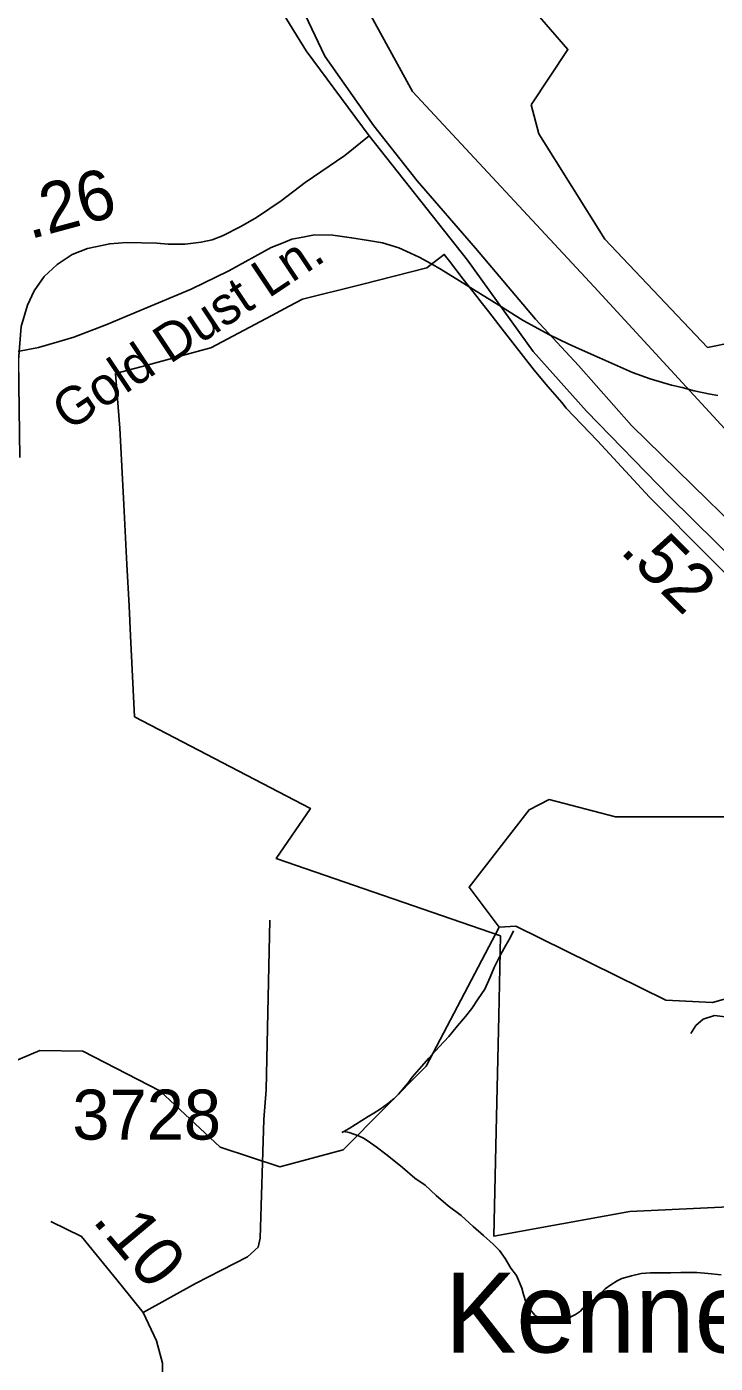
# Model space of a CAD drawing. Extents: x 2001466 to 2224147, y 644118 to 847247.
# Drawn here: x 2072387 to 2074109, y 650618 to 653960 of the extents above; entities that cross this region are included whole.
import ezdxf

# ---------------------------------------------------------------- set-up
doc = ezdxf.new("R2010")
doc.units = 0
for name, color, linetype in [('Exist Aviation Public Landing Strip paved', 7, 'Continuous'), ('Exist Boundary Political City Limit New', 7, 'Continuous'), ('Exist Civil Demographics Community Label', 7, 'Continuous'), ('Exist Hydrographic Misc Water Feature', 7, 'Continuous'), ('Exist Railroad Mainline', 7, 'Continuous'), ('Exist Road Non-System Type 51', 7, 'Continuous'), ('Exist Road Primary NC Attributed', 7, 'Continuous'), ('Exist Road Primary NC Service Mileage Hundredths English Label', 7, 'Continuous'), ('Exist Road Secondary Mileage Hundredths English Label', 7, 'Continuous'), ('Exist Road Secondary Type 51 Attributed', 7, 'Continuous'), ('Exist Road Secondary Type 51 Label', 7, 'Continuous'), ('Exist Road Secondary Type 51 Number Label', 7, 'Continuous'), ('Map Preparation Boundary City Limit Buffer Line', 7, 'Continuous')]:
    doc.layers.add(name, color=color, linetype=linetype)

msp = doc.modelspace()

# ---------------------------------------------------------------- linework, layer by layer
at = {"layer": 'Exist Aviation Public Landing Strip paved'}
msp.add_lwpolyline([(2075026.1, 652255.3), (2074894.2, 652255.3), (2074788.8, 652275.1), (2074657, 652367.4), (2074334, 652736.7), (2073806.7, 653310.3), (2073351.9, 653798.2), (2073206.2, 654065.5), (2073437.6, 654253.2), (2073740.8, 653903.7), (2073648.5, 653765.3), (2073668.3, 653692.7), (2073833, 653429), (2074090.1, 653158.7), (2074156, 653171.9), (2074248.3, 653251), (2074867.9, 652644.4), (2075006.3, 652459.7), (2075012.9, 652334.5), (2075026.1, 652255.3)], dxfattribs=at)
at = {"layer": 'Exist Boundary Political City Limit New'}
msp.add_lwpolyline([(2074160.8, 651010.1), (2073895.5, 650997.6), (2073555.4, 650936.3), (2073561.1, 651198.3), (2073567.6, 651486.8), (2073572.1, 651687), (2073011.2, 651880.7), (2073096.5, 652005.9), (2072656.8, 652235.1), (2072646.8, 652437.2), (2072643, 652512.2), (2072637.6, 652615.8), (2072629.9, 652765.7), (2072620, 652956.5), (2072609.4, 653093), (2072688.1, 653114.4), (2072831.5, 653153.5), (2072847.8, 653157.8), (2072999.8, 653238.4), (2073043.9, 653261.8), (2073076.6, 653279.2), (2073224.4, 653316.2), (2073388, 653357.2), (2073414, 653377.5), (2073431.5, 653391.1), (2073444.6, 653374.6), (2073478.6, 653329.2), (2073512.6, 653286.1), (2073523.9, 653271.7), (2073542.9, 653247.1), (2073576, 653204.3), (2073656.6, 653101.9), (2073690.5, 653060.4), (2073725.8, 653020.4), (2073736.8, 653006.6), (2073814.5, 652924.9), (2073944.6, 652784.2), (2074844, 651880.9)], dxfattribs=at)
at = {"layer": 'Exist Hydrographic Misc Water Feature'}
msp.add_line((2074096.3, 653042), (2074115.8, 653038), dxfattribs=at)
for points in [[(2073028.8, 653420.2), (2073050.5, 653429), (2073077.6, 653434.2)], [(2073028.8, 653420.2), (2073050.5, 653429), (2073077.6, 653434.2)], [(2073077.6, 653434.2), (2073106.7, 653439.9), (2073153, 653439), (2073182.2, 653435.1)], [(2073077.6, 653434.2), (2073106.7, 653439.9), (2073153, 653439), (2073182.2, 653435.1)], [(2073182.2, 653435.1), (2073199.8, 653432.9), (2073241.8, 653425.7)], [(2073182.2, 653435.1), (2073199.8, 653432.9), (2073241.8, 653425.7)], [(2073241.8, 653425.7), (2073276.7, 653419.8), (2073317.9, 653407.9), (2073346.8, 653394.3)], [(2073241.8, 653425.7), (2073276.7, 653419.8), (2073317.9, 653407.9), (2073346.8, 653394.3)], [(2072635.1, 653235.6), (2072798.5, 653304.5), (2072892.8, 653349.9), (2072998.6, 653408.1), (2073028.8, 653420.2)], [(2072635.1, 653235.6), (2072798.5, 653304.5), (2072892.8, 653349.9), (2072998.6, 653408.1), (2073028.8, 653420.2)], [(2073346.8, 653394.3), (2073368.8, 653384.2), (2073397.5, 653368.1)], [(2073346.8, 653394.3), (2073368.8, 653384.2), (2073397.5, 653368.1)], [(2073397.5, 653368.1), (2073423.9, 653353.4), (2073567.7, 653263.8)], [(2073397.5, 653368.1), (2073423.9, 653353.4), (2073567.7, 653263.8)], [(2073567.7, 653263.8), (2073628.8, 653225.8), (2073694.8, 653190), (2073741.5, 653167.6)], [(2073567.7, 653263.8), (2073628.8, 653225.8), (2073694.8, 653190), (2073741.5, 653167.6)], [(2072468.4, 653173.3), (2072504.7, 653184), (2072587.7, 653215.6), (2072635.1, 653235.6)], [(2072468.4, 653173.3), (2072504.7, 653184), (2072587.7, 653215.6), (2072635.1, 653235.6)], [(2072342.7, 653144.5), (2072416.7, 653158), (2072468.4, 653173.3)], [(2072342.7, 653144.5), (2072416.7, 653158), (2072468.4, 653173.3)], [(2073741.5, 653167.6), (2073768.6, 653154.7), (2073820.1, 653132.2)], [(2073741.5, 653167.6), (2073768.6, 653154.7), (2073820.1, 653132.2)], [(2073820.1, 653132.2), (2073902.7, 653096), (2073946.6, 653079.9)], [(2073820.1, 653132.2), (2073902.7, 653096), (2073946.6, 653079.9)], [(2073946.6, 653079.9), (2073999.7, 653064.5), (2074026.4, 653057.9)], [(2073946.6, 653079.9), (2073999.7, 653064.5), (2074026.4, 653057.9)], [(2074026.4, 653057.9), (2074056.9, 653050.2), (2074096.3, 653042)], [(2074026.4, 653057.9), (2074056.9, 653050.2), (2074096.3, 653042)], [(2073568.7, 651708.7), (2073493.6, 651808.7), (2073643.7, 652002.5), (2073693.8, 652027.7), (2073859.7, 651984.9), (2074176.7, 651985), (2074448.4, 651957.8)], [(2072946.5, 651133.7), (2073019.8, 651109.6), (2073178.7, 651152.4), (2073386.6, 651361.4), (2073568.7, 651708.7)], [(2073604.4, 651699.9), (2073596.4, 651681.9), (2073584.3, 651661.9), (2073572.4, 651639.9), (2073556.4, 651607.8), (2073546.5, 651583.8), (2073532.6, 651553.8), (2073516.6, 651529.7), (2073500.6, 651505.7), (2073484.6, 651485.7), (2073464.7, 651461.7), (2073442.8, 651435.6), (2073418.8, 651409.6), (2073393, 651381.5), (2073369, 651353.5), (2073351.1, 651333.5), (2073341.1, 651319.5), (2073331, 651307.5), (2073317.1, 651291.4), (2073305.2, 651279.4), (2073289.2, 651267.4), (2073271.2, 651253.4), (2073255.2, 651243.4), (2073241.2, 651235.3), (2073225.2, 651225.3), (2073209.2, 651215.2), (2073193.2, 651205.2), (2073179.9, 651197.7), (2073175.4, 651195.2)], [(2074449.2, 651617.6), (2074102.6, 651520.8), (2073985.8, 651526.4), (2073610.7, 651711.2), (2073568.7, 651708.7)], [(2070697, 649864.9), (2070730.6, 650053.8), (2070930.7, 650472.9), (2071104.8, 650722), (2071270.7, 650905.6), (2071545.6, 651096.9), (2071870.7, 651241.3), (2072161.6, 651291.1), (2072419.8, 651400.7), (2072527.6, 651398.4), (2072719.8, 651299.4), (2072870.7, 651158.6), (2072946.5, 651133.7)], [(2073175.4, 651195.2), (2073179.9, 651197.7), (2073193.2, 651195.2), (2073205.3, 651191.2), (2073217.2, 651187.3), (2073229.3, 651181.3), (2073241.2, 651173.3), (2073261.3, 651159.3), (2073285.5, 651141.4), (2073305.4, 651125.4), (2073327.3, 651107.5), (2073357.5, 651081.5), (2073383.5, 651063.6), (2073411.6, 651037.6), (2073441.6, 651011.8), (2073473.7, 650987.8), (2073503.7, 650959.9), (2073529.7, 650937.9), (2073553.7, 650916), (2073569.7, 650900), (2073583.9, 650880.1), (2073597.8, 650856.1), (2073612, 650838.1), (2073620, 650820.1), (2073625.9, 650806.1), (2073630, 650790.1), (2073635.9, 650772.2), (2073640, 650762.2), (2073650.1, 650748.2), (2073658.1, 650738.2), (2073667.9, 650732.2), (2073682.1, 650726.2), (2073690.1, 650724.2), (2073700.1, 650722.3), (2073710, 650720.3), (2073718, 650722.3), (2073726, 650724.3), (2073742, 650730.4), (2073748.1, 650734.4), (2073760, 650740.4), (2073772.1, 650748.4), (2073778, 650756.4), (2073792, 650768.4), (2073803.9, 650776.5), (2073817.8, 650788.5), (2073833.8, 650804.5), (2073848, 650814.6), (2073863.8, 650824.5), (2073875.9, 650830.6), (2073899.8, 650836.6), (2073923.8, 650842.7), (2073947.8, 650844.7), (2073973.9, 650844.7), (2073997.9, 650844.8), (2074023.7, 650844.9), (2074063.7, 650844.9), (2074091.8, 650843), (2074123.8, 650839.1)]]:
    msp.add_lwpolyline(points, dxfattribs=at)
at = {"layer": 'Exist Railroad Mainline'}
msp.add_lwpolyline([(2074447.8, 652429.1), (2074089.7, 652777), (2073899.5, 652963), (2073767.5, 653112.9), (2073659.5, 653228.9), (2073509.3, 653406.7), (2073363.3, 653574.7), (2073255.2, 653712.7), (2073133.1, 653886.6), (2073043, 654076.6), (2072967, 654272.8), (2072914.7, 654476.6), (2072848.5, 654812.8), (2072811.5, 655023.4), (2072778.4, 655210.8), (2072702.2, 655610.9), (2072633.9, 656000.9), (2072585.7, 656437.2), (2072559.3, 656635.2), (2072537.3, 656822.6)], dxfattribs=at)
at = {"layer": 'Exist Road Non-System Type 51'}
for points in [[(2072678.2, 650745.3), (2072809.3, 650817.6), (2072938.9, 650884.5), (2072965.6, 650908.6), (2072971, 650931.3), (2072980.3, 651228.2), (2072985.7, 651301.7), (2072995, 651726.4)], [(2074147.4, 651483), (2074107.5, 651487.8), (2074079.3, 651478.4), (2074061, 651462.7), (2074048.5, 651443)]]:
    msp.add_lwpolyline(points, dxfattribs=at)
at = {"layer": 'Exist Road Primary NC Attributed'}
for points in [[(2073243.5, 653687.9), (2073085.9, 653900.1), (2073002.7, 654036.3), (2072949.3, 654163), (2072905.3, 654306.5), (2072862.9, 654505.4), (2072821.6, 654799.7), (2072790.2, 655036.4), (2072748.4, 655193.5), (2072710.7, 655340.1), (2072652.1, 655493)], [(2075058.1, 651633.9), (2074984.8, 651747), (2074910.5, 651840.2), (2074764.5, 651996.2), (2074516, 652245.5), (2074289.4, 652495.8), (2073995.3, 652785.8), (2073787, 652999.5), (2073653.6, 653148.2), (2073489.3, 653376.5), (2073243.5, 653687.9)]]:
    msp.add_lwpolyline(points, dxfattribs=at)
at = {"layer": 'Exist Road Secondary Type 51 Attributed'}
for points in [[(2073243.5, 653687.9), (2073182.6, 653638.7), (2073083.2, 653571.2), (2073023.3, 653524.7), (2072961.8, 653483.4), (2072922.6, 653460.6), (2072876.4, 653437.5), (2072850.6, 653427.4), (2072823.7, 653421.8), (2072783.2, 653416.9), (2072740.5, 653416.9), (2072712.7, 653418.9), (2072636.2, 653420.9), (2072594.5, 653417.9), (2072539.1, 653405.8), (2072500.4, 653390.6), (2072462.9, 653365.8), (2072430.6, 653335.7), (2072405.4, 653300), (2072389, 653264.4), (2072372.7, 653211), (2072366.7, 653126.3), (2072369.9, 652883)], [(2072726.8, 650535.1), (2072726.8, 650618.6), (2072712, 650674.6), (2072678.2, 650745.3), (2072623.4, 650814), (2072524.1, 650935.5), (2072447.1, 650972.4)]]:
    msp.add_lwpolyline(points, dxfattribs=at)
at = {"layer": 'Map Preparation Boundary City Limit Buffer Line'}
msp.add_lwpolyline([(2074160.8, 651010.1), (2073895.5, 650997.6), (2073555.4, 650936.3), (2073561.1, 651198.3), (2073567.6, 651486.8), (2073572.1, 651687), (2073011.2, 651880.7), (2073096.5, 652005.9), (2072656.8, 652235.1), (2072646.8, 652437.2), (2072643, 652512.2), (2072637.6, 652615.8), (2072629.9, 652765.7), (2072620, 652956.5), (2072609.4, 653093), (2072688.1, 653114.4), (2072831.5, 653153.5), (2072847.8, 653157.8), (2072999.8, 653238.4), (2073043.9, 653261.8), (2073076.6, 653279.2), (2073224.4, 653316.2), (2073388, 653357.2), (2073414, 653377.5), (2073431.5, 653391.1), (2073444.6, 653374.6), (2073478.6, 653329.2), (2073512.6, 653286.1), (2073523.9, 653271.7), (2073542.9, 653247.1), (2073576, 653204.3), (2073656.6, 653101.9), (2073690.5, 653060.4), (2073725.8, 653020.4), (2073736.8, 653006.6), (2073814.5, 652924.9), (2073944.6, 652784.2), (2074844, 651880.9)], dxfattribs=at)

# ---------------------------------------------------------------- texts
at = {"layer": 'Exist Civil Demographics Community Label'}
msp.add_text('Kennebec', height=200, dxfattribs=at).set_placement((2073433.1, 650645.2))
at = {"layer": 'Exist Road Primary NC Service Mileage Hundredths English Label'}
msp.add_text('.52', height=125, rotation=315.391, dxfattribs=at).set_placement((2073868.4, 652647.6))
at = {"layer": 'Exist Road Secondary Mileage Hundredths English Label'}
for s, rotation, p in [('.26', 15.1632, (2072394.5, 653428.5)), ('.10', 309.9258, (2072548.8, 650974.8))]:
    msp.add_text(s, height=125, rotation=rotation, dxfattribs=at).set_placement(p)
at = {"layer": 'Exist Road Secondary Type 51 Label'}
msp.add_text('Gold Dust Ln.', height=95, rotation=33.6618, dxfattribs=at).set_placement((2072492.4, 652947.5))
at = {"layer": 'Exist Road Secondary Type 51 Number Label'}
msp.add_text('3728', height=125, dxfattribs=at).set_placement((2072501.2, 651177.6))

doc.saveas('drawing.dxf')
